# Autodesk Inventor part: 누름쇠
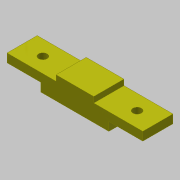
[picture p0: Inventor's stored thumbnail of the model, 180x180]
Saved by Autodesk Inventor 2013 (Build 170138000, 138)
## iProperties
Created: 2019-06
Part Number: 누름쇠
Material: 스테인리스강
Document SubType Name: Modeling
Designer: mduedu
Density: 8.08 g/cm^3
Mass: 69.4303 g
Surface Area: 38.4362 cm^2
Volume: 8.59286 cm^3
Author: mduedu
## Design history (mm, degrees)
sketch "스케치1"
  geometry: L1 (-36, 0)-(36, 0); L2 (36, 0)-(36, 12); L3 (36, 12)-(-36, 12); L4 (-36, 12)-(-36, 0); 2 further points
  constraints: 8 end point, 2 parallel, 1 coincident, 1 horizontal, 1 midpoint, 1 perpendicular
  dimensions: "d0" = 72 distance of L1.start L1.end; "d2" = 12 distance of L1.end L2.end
extrude "돌출1" new body sketch "스케치1" stored distance "d3" = 16; taper "d4" = 0 deg
sketch "스케치2"
  geometry: L1 (-36, 0)-(36, 0) reference; L2 (36, 0)-(36, 12) reference; L3 (36, 12)-(-36, 12) reference; L4 (-36, 12)-(-36, 0) reference; L5 (0, 0)-(0, 12); L6 (-36, 0)-(-18, 0); L7 (-18, 0)-(-18, 4.5); L8 (-18, 4.5)-(-36, 4.5); L9 (-36, 4.5)-(-36, 0); L10 (-36, 12)-(-10, 12); L11 (-10, 12)-(-10, 9); L12 (-10, 9)-(-36, 9); L13 (-36, 9)-(-36, 12); L14 (36, 12)-(36, 0); L15 (36, 0)-(18, 0); L16 (18, 0)-(18, 4.5); L17 (18, 4.5)-(36, 4.5); L18 (36, 4.5)-(36, 0); L19 (36, 12)-(10, 12); L20 (10, 12)-(10, 9); L21 (10, 9)-(36, 9); L22 (36, 9)-(36, 12)
  constraints: 36 end point, 6 symmetric about line, 4 parallel, 2 horizontal, 2 perpendicular, 1 midpoint
  dimensions: "d5" = 18 distance between parallel lines of L5 L7; "d7" = 4.5 distance between parallel lines of L1 L8; "d8" = 10 distance between parallel lines of L5 L11; "d9" = 3 distance between parallel lines of L12 L3
extrude "돌출2" cut sketch "스케치2" stored distance "d10" = 16; taper "d11" = 0 deg
sketch "스케치3"
  geometry: L1 (26, 0)-(26, 16) reference; L2 (0, 16)-(26, 16) reference; L3 (0, 0)-(0, 16) reference; L4 (26, 0)-(0, 0) reference; L5 (46, 0)-(26, 0) reference; L6 (46, 16)-(46, 0) reference; L7 (46, 16)-(72, 16) reference; L8 (72, 16)-(72, 0) reference; L9 (72, 0)-(46, 0) reference; L10 (26, 16)-(46, 16) reference; L11 (36, 16)-(36, 0); C1 r 2.25 at (11, 8); C2 r 2.25 at (61, 8); 1 further point
  constraints: 2 centre point, 2 end point, 2 midpoint, 1 horizontal alignment, 1 symmetric about line, 1 other
  dimensions: "d12" = 4.5 diameter of C1; "d13" = 25 distance of C1.centre point (36, 8)
extrude "돌출3" cut sketch "스케치3" stored distance "d14" = 16; taper "d15" = 0 deg
node "솔리드1"
node "투영된 루프1"
node "절단 모서리 투영1"
